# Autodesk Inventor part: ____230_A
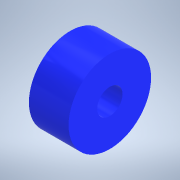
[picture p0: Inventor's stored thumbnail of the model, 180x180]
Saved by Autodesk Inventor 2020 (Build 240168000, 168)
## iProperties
Created: 2017-09
Part Number: ____230_A
Material: Générique
Document SubType Name: Modeling
Designer: bruno
Density: 1 g/cm^3
Appearance: Bleu - Peinture murale - Brillant
Mass: 6.0083 g
Surface Area: 22.965 cm^2
Volume: 6.0083 cm^3
Sending System: SolidWorks 2016
Last Author: Prof
Last Saved: 2018-10-03
Author: bruno
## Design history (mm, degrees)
feature "Enlèv. mat.-Extru.1"
node "Solide1"
